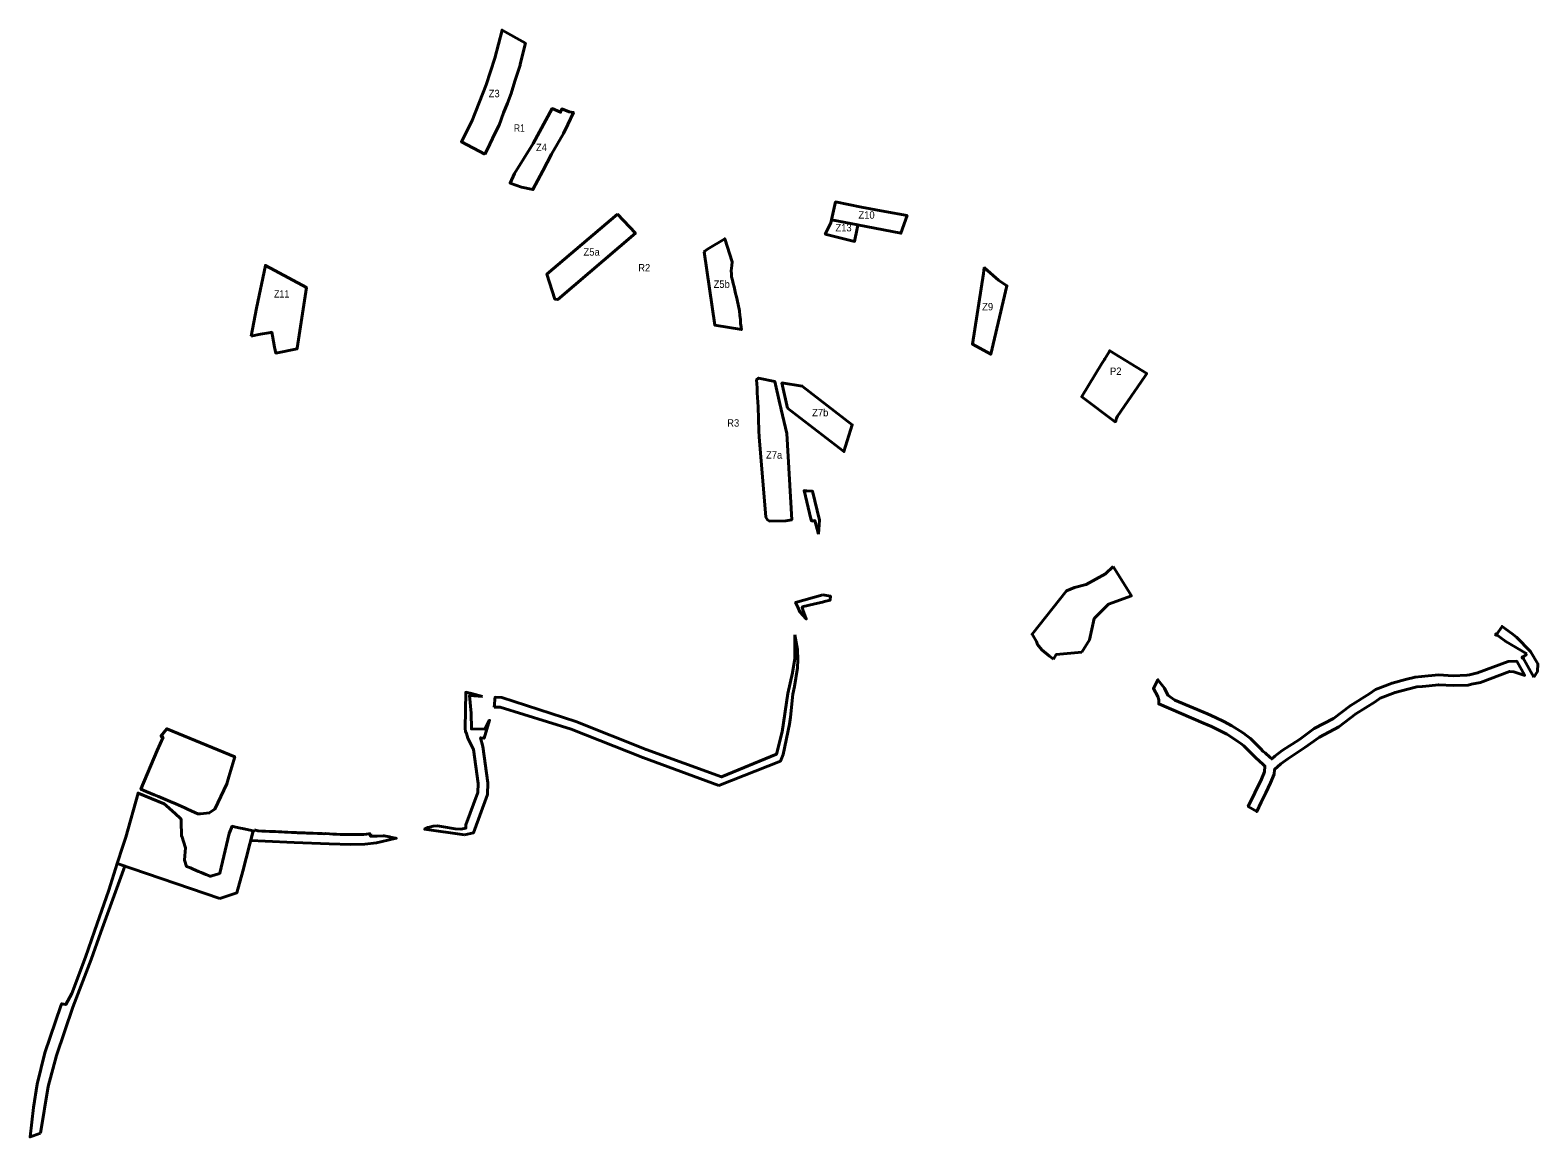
# Model space of a CAD drawing. Extents: x -555426 to -553131, y -1186725 to -1183160.
# Drawn here: x -555426 to -553131, y -1186725 to -1185042 of the extents above; entities that cross this region are included whole.
import ezdxf
from ezdxf.enums import TextEntityAlignment as Align

# ---------------------------------------------------------------- set-up
doc = ezdxf.new("R2010")
doc.units = 0
doc.header["$LTSCALE"] = 4.5
doc.header["$PDMODE"] = 32
doc.header["$PDSIZE"] = 2.25
for name, color, linetype, lineweight in [('12', 7, 'Continuous', 40), ('17', 7, 'Continuous', 40), ('2', 7, 'Continuous', 40), ('48', 7, 'Continuous', 40), ('6', 7, 'Continuous', 40), ('62', 7, 'Continuous', 25), ('8', 7, 'Continuous', 40)]:
    doc.layers.add(name, color=color, linetype=linetype, lineweight=lineweight)
for name, color, linetype in [('59', 7, 'Continuous'), ('60', 7, 'Continuous'), ('61', 7, 'Continuous')]:
    doc.layers.add(name, color=color, linetype=linetype)

msp = doc.modelspace()

# ---------------------------------------------------------------- linework, layer by layer
at = {"layer": '12'}
msp.add_lwpolyline([(-553973.359, -1185402.641), (-553974.35, -1185411.9), (-553991.445, -1185519.302), (-553963.43, -1185534.75), (-553938.9, -1185430.55), (-553951.92, -1185422.15), (-553972.449, -1185403.469)], close=True, dxfattribs=at)
at = {"layer": '17'}
msp.add_lwpolyline([(-554205.92, -1185330.047), (-554207, -1185334.66), (-554207.96, -1185336.64), (-554215.313, -1185351.817), (-554207.47, -1185353.77), (-554170.793, -1185362.901), (-554167.012, -1185343.092), (-554166.009, -1185337.836)], close=True, dxfattribs=at)
at = {"layer": '2'}
for points in [[(-554733.51, -1185230.02), (-554730.2, -1185223.52), (-554717.59, -1185197.71), (-554711.77, -1185186.23), (-554704.88, -1185167.56), (-554699.12, -1185152.43), (-554693.52, -1185137.73), (-554687.65, -1185119.22), (-554679.93, -1185094.89), (-554679.52, -1185093.4), (-554671.85, -1185061.39), (-554707.18, -1185041.55), (-554718.485, -1185084.142), (-554731.329, -1185124.63), (-554753.057, -1185179.2), (-554769.052, -1185211.233)], [(-554688.42, -1185259.67), (-554694.99, -1185274.23), (-554677.59, -1185280.44), (-554660.25, -1185284.19), (-554645.24, -1185255.79), (-554631.94, -1185230), (-554613.87, -1185198.73), (-554607.1, -1185184.92), (-554598.76, -1185166.79), (-554605.12, -1185165.73), (-554616.11, -1185161.44), (-554616.48, -1185161.3), (-554618.25, -1185166.48), (-554630.97, -1185160.97), (-554660.04, -1185213.75)], [(-554531.777, -1185321.491), (-554638.923, -1185412.788), (-554627.182, -1185450.638), (-554622.556, -1185451.394), (-554504.308, -1185350.637)], [(-554399.867, -1185378.779), (-554398.64, -1185377.82), (-554394.81, -1185374.96), (-554368.27, -1185358.89), (-554357.24, -1185393.87), (-554357.73, -1185399.4), (-554358.1, -1185403.56), (-554358.55, -1185407.8), (-554358.24, -1185412.39), (-554357.86, -1185417.02), (-554356.48, -1185422.06), (-554355.39, -1185427.08), (-554354.3, -1185432.1), (-554353.02, -1185437.14), (-554351.77, -1185442.03), (-554350.5, -1185447.06), (-554348.02, -1185459.19), (-554346.15, -1185468.55), (-554345.29, -1185475.74), (-554344.6, -1185481.98), (-554344.16, -1185487.64), (-554343.59, -1185493), (-554343.144, -1185497.196), (-554383.322, -1185490.608)], [(-554305.651, -1185782.363), (-554303.28, -1185786.68), (-554300.2, -1185788.59), (-554275.27, -1185787.98), (-554266.32, -1185786.4), (-554273.88, -1185655.23), (-554282.43, -1185618.58), (-554282.94, -1185616.37), (-554284.34, -1185610.24), (-554292.21, -1185575.92), (-554316.867, -1185570.895), (-554319.852, -1185573.671), (-554319.21, -1185586), (-554318.84, -1185593.32), (-554317.73, -1185614.65), (-554316.26, -1185651.34), (-554315.85, -1185660.44)], [(-554272.647, -1185616.49), (-554281.413, -1185578.266), (-554250.477, -1185583.069), (-554174.425, -1185641.889), (-554187.013, -1185682.721)]]:
    msp.add_lwpolyline(points, close=True, dxfattribs=at)
at = {"layer": '48'}
for p, q in [((-553147.76, -1185990.72), (-553153.84, -1185996.12)), ((-553153.84, -1185996.12), (-553136.76, -1186025.81))]:
    msp.add_line(p, q, dxfattribs=at)
for points in [[(-554225.516, -1185808.234), (-554224.11, -1185787.364), (-554234.745, -1185743.116), (-554244.07, -1185742.37), (-554247.64, -1185742.08), (-554237.39, -1185785.09)], [(-554237.39, -1185785.09), (-554235.75, -1185788.44), (-554231.18, -1185787.69), (-554225.516, -1185808.234)], [(-553777.28, -1185857.816), (-553788.665, -1185868.775), (-553818.407, -1185885.262), (-553836.143, -1185889.543), (-553848.116, -1185894.514), (-553900.68, -1185960.74), (-553893.92, -1185971.59), (-553892.19, -1185976.11), (-553885.57, -1185984.25)], [(-553825.075, -1185988.124), (-553813.195, -1185969.073), (-553806.078, -1185936.966), (-553784.191, -1185915.024), (-553749.515, -1185902.394), (-553777.28, -1185857.816)], [(-554219.04, -1185900.71), (-554260.557, -1185912.173), (-554256.71, -1185920.61), (-554254.1, -1185926.61), (-554244.35, -1185937.42), (-554249.57, -1185923.77), (-554250.31, -1185919.09), (-554231.43, -1185914.6)], [(-554231.43, -1185914.6), (-554219.41, -1185911.75), (-554216.82, -1185911.13), (-554207.981, -1185909.04), (-554207.51, -1185902.62), (-554219.04, -1185900.71)], [(-553136.76, -1186025.81), (-553131.636, -1186017.15), (-553130.875, -1186005.959), (-553141.815, -1185986.942), (-553163.584, -1185965.017), (-553170.649, -1185959.736), (-553185.396, -1185948.905), (-553193.99, -1185961.2)], [(-554261.93, -1185961.69), (-554261.867, -1185997.814), (-554265.332, -1186019.412), (-554272.29, -1186050.65), (-554281.22, -1186109.23), (-554289.524, -1186142.992), (-554373.27, -1186177.71), (-554488.13, -1186136.21), (-554595.17, -1186093.44), (-554707.698, -1186057.015), (-554717.81, -1186056.56), (-554718.22, -1186060.11), (-554719.05, -1186067.25), (-554719.544, -1186071.497)], [(-554377.29, -1186191), (-554283.71, -1186153.97), (-554279.71, -1186143.62), (-554270.02, -1186097.65), (-554268.36, -1186086.78), (-554265, -1186051.94), (-554262.02, -1186040.25), (-554257.45, -1186011.8), (-554256.93, -1185999.75), (-554257.84, -1185983.71), (-554261.93, -1185961.69)], [(-553193.99, -1185961.2), (-553189.33, -1185964.5), (-553179.63, -1185971.75), (-553147.76, -1185990.72)], [(-553885.57, -1185984.25), (-553874.36, -1185993.93), (-553868.12, -1185998.62)], [(-553868.12, -1185998.62), (-553864.032, -1185991.549), (-553825.075, -1185988.124)], [(-554737.11, -1186055.23), (-554753.62, -1186050.71), (-554762.47, -1186048.86), (-554763.69, -1186104.04), (-554763.13, -1186108.53), (-554761.3, -1186111.92), (-554759.33, -1186118.73), (-554750.96, -1186135.85), (-554743.83, -1186187.67), (-554744.21, -1186201.47), (-554762.32, -1186250.8), (-554762.42, -1186255.74), (-554769.94, -1186257.54), (-554778.46, -1186256.89), (-554796.4, -1186253.91), (-554805.74, -1186252.36), (-554812.08, -1186252.63), (-554817.93, -1186254.2), (-554820.52, -1186254.89), (-554825.122, -1186257.297), (-554764.262, -1186265.676)], [(-554764.262, -1186265.676), (-554750.84, -1186263.055), (-554729.283, -1186204.336), (-554728.802, -1186186.849), (-554736.428, -1186131.423), (-554740.112, -1186118.075), (-554734.72, -1186119), (-554726.42, -1186091.6), (-554733.53, -1186104.88), (-554754.02, -1186104.78), (-554754.21, -1186080.59), (-554756.79, -1186053.88), (-554737.11, -1186055.23)], [(-554719.544, -1186071.497), (-554710.393, -1186071.909), (-554602.25, -1186105.03), (-554493.14, -1186148.4), (-554377.29, -1186191)], [(-555084.2, -1186258.4), (-555084.7, -1186260.33), (-555086.13, -1186260.01), (-555089.854, -1186274.456)], [(-554906.96, -1186263.94), (-554913.63, -1186264.75), (-554917.47, -1186265.28), (-554919.39, -1186265.33), (-554927.11, -1186265.47), (-554932.26, -1186265.55), (-554936.56, -1186265.5), (-554937.11, -1186265.47), (-554942.03, -1186265.63), (-554947.66, -1186265.42), (-554953.66, -1186265.32), (-554959.36, -1186264.92), (-554961.69, -1186264.81), (-554964.83, -1186264.67), (-554969.85, -1186264.42), (-554976.07, -1186264.1), (-554978.07, -1186264.16), (-554981.59, -1186263.95), (-554986.25, -1186263.91), (-554987.98, -1186263.78), (-554994.91, -1186263.58), (-555001.35, -1186263.21), (-555004.22, -1186263.18), (-555007.26, -1186263.05), (-555012.37, -1186262.95), (-555013.89, -1186263.01), (-555018.64, -1186262.69), (-555020.77, -1186262.57), (-555022.88, -1186262.45), (-555027.97, -1186262.21), (-555033.35, -1186261.86), (-555037.22, -1186261.67), (-555038.25, -1186261.63), (-555042.62, -1186261.45), (-555045.15, -1186261.2), (-555047.35, -1186261.3), (-555052.31, -1186261.05), (-555057.13, -1186260.95), (-555060.21, -1186260.69), (-555061.43, -1186260.68), (-555067.24, -1186260.4), (-555072.69, -1186260.16), (-555077.96, -1186259.94), (-555079.09, -1186259.62), (-555084.2, -1186258.4)], [(-554937.275, -1186280.483), (-554916.246, -1186280.253), (-554898.31, -1186277.981), (-554881.215, -1186274.099), (-554868.43, -1186271.13), (-554869.06, -1186271.01), (-554877.64, -1186269.36), (-554878.85, -1186269.12), (-554886.77, -1186267.56), (-554887.87, -1186267.31), (-554897.58, -1186268.01), (-554907.83, -1186267.84), (-554906.96, -1186263.94)], [(-555089.854, -1186274.456), (-555067.931, -1186275.384), (-555023.659, -1186277.43), (-554970.608, -1186279.401), (-554937.275, -1186280.483)], [(-555409.6, -1186719.66), (-555398.08, -1186648.64), (-555385.52, -1186601.65), (-555360.47, -1186527.99), (-555332.87, -1186455.38), (-555317.95, -1186413.97), (-555281.216, -1186313.355), (-555292.95, -1186309.355), (-555305.75, -1186349.85), (-555327.86, -1186412.63), (-555341.32, -1186452.09), (-555362.31, -1186507.34), (-555371.26, -1186524.24), (-555374.35, -1186523.58)], [(-555374.35, -1186523.58), (-555377.44, -1186522.92), (-555378.76, -1186526.22), (-555403.3, -1186597.68)], [(-555403.3, -1186597.68), (-555414.63, -1186645.4), (-555420.53, -1186680.78), (-555425.54, -1186725.43), (-555420.84, -1186723.67), (-555415.22, -1186721.67), (-555409.6, -1186719.66)]]:
    msp.add_lwpolyline(points, dxfattribs=at)
for points in [[(-553548.02, -1186159.66), (-553546.182, -1186161.261), (-553546.991, -1186169.987), (-553551.543, -1186181.231), (-553571.668, -1186222.815), (-553558.79, -1186230.64), (-553551.72, -1186216.33), (-553544.71, -1186202.05), (-553537.64, -1186186.86), (-553532.26, -1186173.57), (-553531.6, -1186166.45), (-553521.79, -1186158.06), (-553511.19, -1186150.03), (-553485.32, -1186133.04), (-553463.3, -1186117.12), (-553433.95, -1186101.46), (-553408.08, -1186081.8), (-553378.55, -1186063.63), (-553370.87, -1186058.18), (-553348.08, -1186049.28), (-553328.68, -1186044.22), (-553315.27, -1186040.84), (-553306.3, -1186040.1), (-553306.3, -1186040.1), (-553281.66, -1186037.48), (-553281.66, -1186037.48), (-553259.77, -1186038.75), (-553237.04, -1186038), (-553231.86, -1186036.89), (-553218.26, -1186033.91), (-553173.99, -1186017.29), (-553167.22, -1186018.11), (-553150.76, -1186023.24), (-553162.91, -1186001.77), (-553175.828, -1186001.958), (-553222.523, -1186019.488), (-553235.037, -1186022.23), (-553238.873, -1186023.052), (-553259.583, -1186023.736), (-553282.021, -1186022.434), (-553307.71, -1186025.165), (-553317.736, -1186025.993), (-553332.406, -1186029.69), (-553352.717, -1186034.988), (-553378.046, -1186044.879), (-553386.83, -1186051.112), (-553416.569, -1186069.411), (-553442.07, -1186088.791), (-553471.261, -1186104.366), (-553493.836, -1186120.687), (-553519.846, -1186137.769), (-553531.202, -1186146.372), (-553535.863, -1186150.358), (-553538.103, -1186148.406), (-553546.022, -1186141.348), (-553548.683, -1186138.882), (-553553.043, -1186134.503), (-553557.145, -1186130.6), (-553560.554, -1186127.153), (-553563.838, -1186123.82), (-553568.263, -1186119.334), (-553574.069, -1186114.956), (-553578.7, -1186111.427), (-553584.623, -1186107.599), (-553596.515, -1186099.928), (-553608.823, -1186093.668), (-553621.239, -1186087.362), (-553633.865, -1186082.054), (-553683.475, -1186060.759), (-553694.198, -1186053.632), (-553699.051, -1186042.658), (-553709.22, -1186029.91), (-553714.54, -1186040.11), (-553715.99, -1186043.02), (-553709.24, -1186055.23), (-553707.92, -1186060.73), (-553707.78, -1186066.65), (-553639.73, -1186095.86), (-553627.55, -1186100.98), (-553615.62, -1186107.04), (-553604, -1186112.95), (-553592.76, -1186120.2), (-553587.33, -1186123.71), (-553583.13, -1186126.91), (-553578.17, -1186130.65), (-553574.52, -1186134.35), (-553571.23, -1186137.69), (-553567.65, -1186141.31), (-553563.53, -1186145.23), (-553559.1, -1186149.68), (-553556.11, -1186152.45)], [(-555185.99, -1186226.72), (-555175.06, -1186231.77), (-555170.16, -1186234.03), (-555166.5, -1186233.72), (-555157.32, -1186232.94), (-555153.01, -1186232.57), (-555146, -1186227.85), (-555144.69, -1186226.97), (-555126.25, -1186188.5), (-555123.11, -1186177.66), (-555114.26, -1186147.16), (-555217.36, -1186104.58), (-555226.45, -1186115.68), (-555223.12, -1186117.41), (-555232.18, -1186137.72), (-555256.91, -1186196.5), (-555248.77, -1186199.76), (-555242.74, -1186202.33), (-555236.71, -1186204.91), (-555230.2, -1186207.64), (-555212.56, -1186215.1), (-555203.72, -1186218.85), (-555194.89, -1186222.61), (-555190.05, -1186224.85)], [(-555136.764, -1186362.594), (-555110.731, -1186353.98), (-555101.91, -1186321.23), (-555086.13, -1186260.01), (-555093.4, -1186258.38), (-555100.06, -1186256.89), (-555107.79, -1186255.16), (-555114.53, -1186253.65), (-555117.88, -1186252.9), (-555122.79, -1186264.03), (-555136.85, -1186324.41), (-555138.36, -1186325.06), (-555142.52, -1186326.28), (-555150.68, -1186328.68), (-555151.71, -1186328.98), (-555157.95, -1186326.36), (-555165.36, -1186323.24), (-555169.27, -1186321.6), (-555177.22, -1186318.25), (-555181.71, -1186316.36), (-555186.26, -1186314.45), (-555187.71, -1186313.84), (-555190.76, -1186304.59), (-555190.1, -1186297.86), (-555188.93, -1186285.88), (-555194.7, -1186268.11), (-555195.22, -1186267.63), (-555195.64, -1186245.84), (-555195.72, -1186241.89), (-555197.18, -1186240.55), (-555204.2, -1186234.11), (-555218.31, -1186221.15), (-555221.4, -1186218.64), (-555261.28, -1186202.32), (-555279.68, -1186269.64), (-555284.72, -1186283.32), (-555292.95, -1186309.355)]]:
    msp.add_lwpolyline(points, close=True, dxfattribs=at)
for p in [(-553193.99, -1185961.2), (-553153.84, -1185996.12)]:
    msp.add_point(p, dxfattribs=at)
at = {"layer": '6'}
msp.add_lwpolyline([(-554205.92, -1185330.047), (-554100.379, -1185350.644), (-554090.82, -1185323.71), (-554124.84, -1185317.69), (-554160.01, -1185310.95), (-554199.59, -1185303)], close=True, dxfattribs=at)
at = {"layer": '62'}
for points in [[(-554707.18, -1185041.55), (-554671.85, -1185061.39), (-554679.52, -1185093.4), (-554679.93, -1185094.89), (-554687.65, -1185119.22), (-554693.52, -1185137.73), (-554699.12, -1185152.43), (-554704.88, -1185167.56), (-554711.77, -1185186.23), (-554717.59, -1185197.71), (-554730.2, -1185223.52), (-554733.51, -1185230.02), (-554769.052, -1185211.233), (-554753.057, -1185179.2), (-554731.329, -1185124.63), (-554718.485, -1185084.142)], [(-554677.59, -1185280.44), (-554660.25, -1185284.19), (-554645.24, -1185255.79), (-554631.94, -1185230), (-554613.87, -1185198.73), (-554607.1, -1185184.92), (-554598.76, -1185166.79), (-554605.12, -1185165.73), (-554616.11, -1185161.44), (-554616.48, -1185161.3), (-554618.25, -1185166.48), (-554630.97, -1185160.97), (-554660.04, -1185213.75), (-554688.42, -1185259.67), (-554694.99, -1185274.23)], [(-554205.92, -1185330.047), (-554100.379, -1185350.644), (-554090.82, -1185323.71), (-554124.84, -1185317.69), (-554160.01, -1185310.95), (-554199.59, -1185303)], [(-554531.777, -1185321.491), (-554638.923, -1185412.788), (-554627.182, -1185450.638), (-554622.556, -1185451.394), (-554504.308, -1185350.637)], [(-554399.867, -1185378.779), (-554398.64, -1185377.82), (-554394.81, -1185374.96), (-554368.27, -1185358.89), (-554357.24, -1185393.87), (-554357.73, -1185399.4), (-554358.1, -1185403.56), (-554358.55, -1185407.8), (-554358.24, -1185412.39), (-554357.86, -1185417.02), (-554356.48, -1185422.06), (-554355.39, -1185427.08), (-554354.3, -1185432.1), (-554353.02, -1185437.14), (-554351.77, -1185442.03), (-554350.5, -1185447.06), (-554348.02, -1185459.19), (-554346.15, -1185468.55), (-554345.29, -1185475.74), (-554344.6, -1185481.98), (-554344.16, -1185487.64), (-554343.59, -1185493), (-554343.144, -1185497.196), (-554383.322, -1185490.608)], [(-555089.21, -1185507), (-555081.04, -1185464.34), (-555067.367, -1185399.402), (-555052.93, -1185407.202), (-555005.1, -1185432.97), (-555013.13, -1185486.02), (-555019.08, -1185525.33), (-555019.241, -1185526.435), (-555051.7, -1185532.91), (-555053.44, -1185523.9), (-555056.79, -1185506.46), (-555057.82, -1185501.14), (-555062.21, -1185501.96), (-555074.79, -1185504.31), (-555079.88, -1185505.26), (-555084.52, -1185506.13)], [(-553938.9, -1185430.55), (-553951.92, -1185422.15), (-553972.449, -1185403.469), (-553973.359, -1185402.641), (-553974.35, -1185411.9), (-553991.445, -1185519.302), (-553963.43, -1185534.75), (-553947.05, -1185465.171)], [(-554273.88, -1185655.23), (-554266.32, -1185786.4), (-554275.27, -1185787.98), (-554300.2, -1185788.59), (-554303.28, -1185786.68), (-554305.651, -1185782.363), (-554315.85, -1185660.44), (-554316.26, -1185651.34), (-554317.73, -1185614.65), (-554318.84, -1185593.32), (-554319.21, -1185586), (-554319.852, -1185573.671), (-554316.867, -1185570.895), (-554292.21, -1185575.92), (-554284.34, -1185610.24), (-554282.94, -1185616.37), (-554282.43, -1185618.58)], [(-554272.647, -1185616.49), (-554281.413, -1185578.266), (-554250.477, -1185583.069), (-554174.425, -1185641.889), (-554187.013, -1185682.721)]]:
    msp.add_lwpolyline(points, close=True, dxfattribs=at)
for points in [[(-554205.92, -1185330.047), (-554207, -1185334.66), (-554207.96, -1185336.64), (-554215.313, -1185351.817), (-554207.47, -1185353.77), (-554170.793, -1185362.901), (-554167.012, -1185343.092), (-554166.009, -1185337.836)], [(-553771.93, -1185632.13), (-553770.83, -1185628.82), (-553729.23, -1185568.43), (-553726.01, -1185563.76), (-553782.49, -1185529.43), (-553782.81, -1185529.95), (-553784.83, -1185533.39), (-553789.98, -1185541.71), (-553790.41, -1185542.52), (-553794.42, -1185548.98), (-553824.8, -1185598.76), (-553825.09, -1185599.26), (-553773.82, -1185637.86), (-553771.508, -1185630.852)]]:
    msp.add_lwpolyline(points, dxfattribs=at)
at = {"layer": '8'}
msp.add_line((-553773.82, -1185637.86), (-553771.93, -1185632.13), dxfattribs=at)
msp.add_lwpolyline([(-555089.21, -1185507), (-555081.04, -1185464.34), (-555067.367, -1185399.402), (-555052.93, -1185407.202), (-555005.1, -1185432.97), (-555013.13, -1185486.02), (-555019.08, -1185525.33), (-555019.241, -1185526.435), (-555051.7, -1185532.91), (-555053.44, -1185523.9), (-555056.79, -1185506.46), (-555057.82, -1185501.14), (-555062.21, -1185501.96), (-555074.79, -1185504.31), (-555079.88, -1185505.26), (-555084.52, -1185506.13)], close=True, dxfattribs=at)
msp.add_lwpolyline([(-553771.93, -1185632.13), (-553770.83, -1185628.82), (-553729.23, -1185568.43), (-553726.01, -1185563.76), (-553782.49, -1185529.43), (-553782.81, -1185529.95), (-553784.83, -1185533.39), (-553789.98, -1185541.71), (-553790.41, -1185542.52), (-553794.42, -1185548.98), (-553824.8, -1185598.76), (-553825.09, -1185599.26), (-553773.82, -1185637.86)], dxfattribs=at)

# ---------------------------------------------------------------- texts
at = {"layer": '59'}
for s, width, p in [('R1', 0.85, (-554689.103, -1185196.126)), ('R2', 0.95, (-554500.089, -1185408.694)), ('R3', 0.95, (-554364.666, -1185644.812))]:
    msp.add_text(s, height=11.25, dxfattribs=dict(at, width=width)).set_placement(p)
at = {"layer": '60'}
for s, width, p in [('Z3', 0.95, (-554719.309, -1185143.558)), ('Z4', 0.95, (-554647.331, -1185225.534)), ('Z10', 0.95, (-554152.556, -1185328.337)), ('Z13', 0.95, (-554187.561, -1185347.732)), ('Z5a', 0.95, (-554571.027, -1185384.61)), ('Z5b', 0.95, (-554373, -1185433.637)), ('Z11', 0.9, (-555042.686, -1185448.443)), ('Z9', 0.95, (-553968.261, -1185467.859)), ('Z7b', 0.95, (-554223.059, -1185629.088)), ('Z7a', 0.95, (-554293.235, -1185693.495))]:
    msp.add_text(s, height=11.25, dxfattribs=dict(at, width=width)).set_placement(p, align=Align.CENTER)
at = {"layer": '61', "width": 0.95}
msp.add_text('P2', height=11.25, dxfattribs=at).set_placement((-553773.304, -1185566.137), align=Align.CENTER)

doc.saveas('drawing.dxf')
